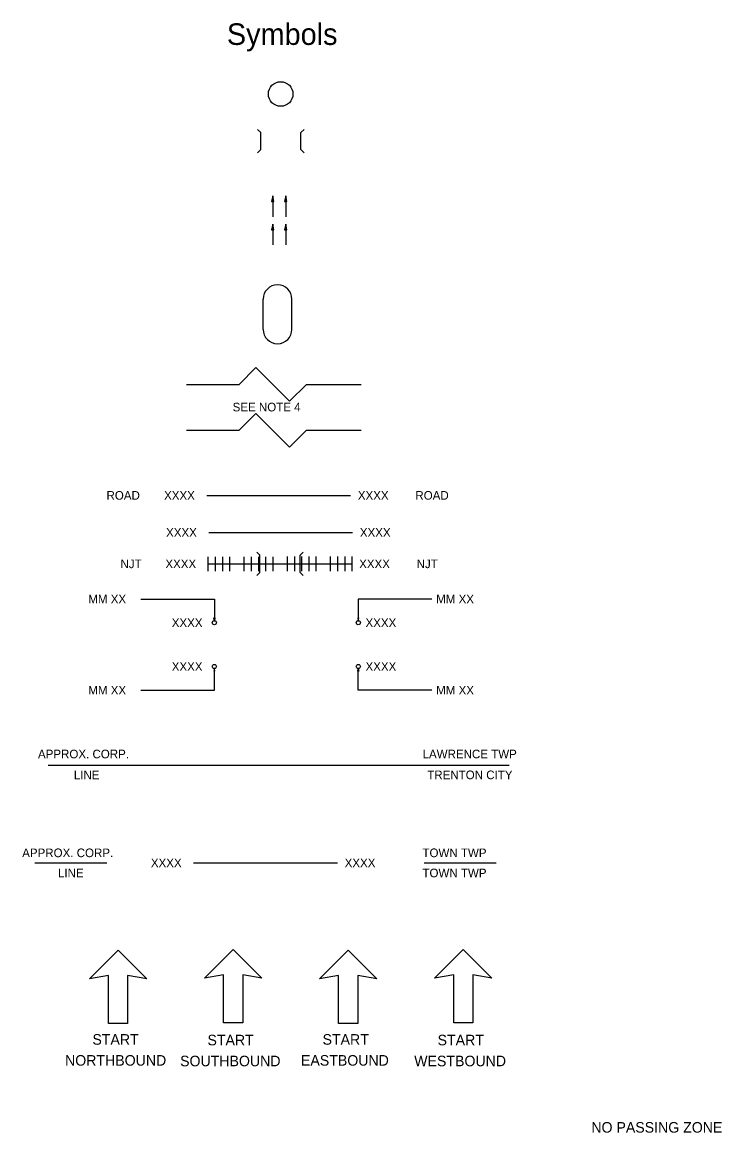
# Model space of a CAD drawing. Extents: x -6359 to 1641, y 3001 to 24737.
# Drawn here: x -4211 to 653, y 3001 to 10724 of the extents above; entities that cross this region are included whole.
import ezdxf

# ---------------------------------------------------------------- set-up
doc = ezdxf.new("R2010")
doc.units = 0
doc.layers.add('_Notes', color=7, linetype='Continuous')

msp = doc.modelspace()

# ---------------------------------------------------------------- linework, layer by layer
at = {"layer": '_Notes'}
for p, q in [((-2553.2, 9957.4), (-2574.4, 9978.6)), ((-2273.2, 9957.4), (-2252, 9978.6)), ((-2553.2, 9837.4), (-2553.2, 9957.4)), ((-2273.2, 9837.4), (-2273.2, 9957.4)), ((-2574.4, 9816.1), (-2553.2, 9837.4)), ((-2252, 9816.1), (-2273.2, 9837.4)), ((-2469.7, 9515.4), (-2469.7, 9370.5)), ((-2379, 9515.4), (-2379, 9370.5)), ((-2469.7, 9319.3), (-2469.7, 9174.4)), ((-2379, 9319.3), (-2379, 9174.4)), ((-2536, 8587.7), (-2536, 8797.7)), ((-2336, 8587.7), (-2336, 8797.7)), ((-2703.4, 8205.1), (-2586.6, 8321.9)), ((-2586.6, 8321.9), (-2352.8, 8088.2)), ((-3068.9, 8205.1), (-2703.4, 8205.1)), ((-2352.8, 8088.2), (-2235.8, 8205.1)), ((-2235.8, 8205.1), (-1853.9, 8205.1)), ((-2703.4, 7885.7), (-2586.6, 8002.5)), ((-2586.6, 8002.5), (-2352.8, 7768.8)), ((-3068.9, 7885.7), (-2703.4, 7885.7)), ((-2352.8, 7768.8), (-2235.8, 7885.7)), ((-2235.8, 7885.7), (-1853.9, 7885.7)), ((-2928.6, 7433.2), (-2428.2, 7433.2)), ((-2428.2, 7433.2), (-1927.7, 7433.2)), ((-2914.6, 7175.7), (-2414.2, 7175.7)), ((-2414.2, 7175.7), (-1913.7, 7175.7)), ((-2559.1, 7017.3), (-2580.3, 7038.5)), ((-2279.1, 7017.3), (-2257.8, 7038.5)), ((-2919.5, 7007.1), (-2919.5, 6907.1)), ((-2919.5, 6957.1), (-2419.1, 6957.3)), ((-2869.5, 7007.1), (-2869.5, 6907.1)), ((-2819.5, 7007.1), (-2819.5, 6907.1)), ((-2769.5, 7007.1), (-2769.5, 6907.1)), ((-2669.5, 7007.1), (-2669.5, 6907.1)), ((-2619.5, 7007.1), (-2619.5, 6907.1)), ((-2569.5, 7007.1), (-2569.5, 6907.1)), ((-2559.1, 6897.3), (-2559.1, 7017.3)), ((-2519.5, 7007.1), (-2519.5, 6907.1)), ((-2469.5, 7007.1), (-2469.5, 6907.1)), ((-2419.1, 6957.3), (-1918.6, 6957.3)), ((-2369.1, 7007.3), (-2369.1, 6907.3)), ((-2319.1, 7007.3), (-2319.1, 6907.3)), ((-2279.1, 6897.3), (-2279.1, 7017.3)), ((-2269.1, 7007.3), (-2269.1, 6907.3)), ((-2219.1, 7007.3), (-2219.1, 6907.3)), ((-2169.1, 7007.3), (-2169.1, 6907.3)), ((-2069.1, 7007.3), (-2069.1, 6907.3)), ((-2019.1, 7007.3), (-2019.1, 6907.3)), ((-1969.1, 7007.3), (-1969.1, 6907.3)), ((-1919.1, 7007.3), (-1919.1, 6907.3)), ((-2580.3, 6876.1), (-2559.1, 6897.3)), ((-2257.8, 6876.1), (-2279.1, 6897.3)), ((-3386.4, 6712), (-2875.3, 6712)), ((-2875.3, 6712), (-2875.3, 6561.8)), ((-1874.4, 6712), (-1874.4, 6561.8)), ((-1363.3, 6712), (-1874.4, 6712)), ((-2875.3, 6079.3), (-2875.3, 6229.4)), ((-1874.4, 6079.3), (-1874.4, 6229.4)), ((-3386.4, 6079.3), (-2875.3, 6079.3)), ((-1363.3, 6079.3), (-1874.4, 6079.3)), ((-4031.2, 5556.5), (-3531.2, 5556.5)), ((-3531.2, 5556.5), (-1324.5, 5556.5)), ((-1324.5, 5556.5), (-824.5, 5556.5)), ((-4123.3, 4877.6), (-3623.3, 4877.6)), ((-3020.4, 4877.6), (-2519.9, 4877.6)), ((-2519.9, 4877.6), (-2019.4, 4877.6)), ((-1416.5, 4877.6), (-916.5, 4877.6)), ((-3744.3, 4072), (-3544.8, 4271.5)), ((-3544.8, 4271.5), (-3345.4, 4072)), ((-2944.3, 4076.3), (-2744.8, 4275.8)), ((-2744.8, 4275.8), (-2545.4, 4076.3)), ((-2144.3, 4072), (-1944.8, 4271.5)), ((-1944.8, 4271.5), (-1745.4, 4072)), ((-1344.3, 4076.3), (-1144.8, 4275.8)), ((-1144.8, 4275.8), (-945.4, 4076.3)), ((-3611.3, 4094.2), (-3744.3, 4072)), ((-3611.3, 3761.7), (-3611.3, 4094.2)), ((-3345.4, 4072), (-3478.3, 4094.2)), ((-3478.3, 4094.2), (-3478.3, 3761.7)), ((-2811.3, 4098.5), (-2944.3, 4076.3)), ((-2811.3, 3766), (-2811.3, 4098.5)), ((-2545.4, 4076.3), (-2678.3, 4098.5)), ((-2678.3, 4098.5), (-2678.3, 3766)), ((-2011.3, 4094.2), (-2144.3, 4072)), ((-2011.3, 3761.7), (-2011.3, 4094.2)), ((-1745.4, 4072), (-1878.3, 4094.2)), ((-1878.3, 4094.2), (-1878.3, 3761.7)), ((-1211.3, 4098.5), (-1344.3, 4076.3)), ((-1211.3, 3766), (-1211.3, 4098.5)), ((-945.4, 4076.3), (-1078.3, 4098.5)), ((-1078.3, 4098.5), (-1078.3, 3766)), ((-3478.3, 3761.7), (-3611.3, 3761.7)), ((-2678.3, 3766), (-2811.3, 3766)), ((-1878.3, 3761.7), (-2011.3, 3761.7)), ((-1078.3, 3766), (-1211.3, 3766))]:
    msp.add_line(p, q, dxfattribs=at)
for points in [[(-2461.7, 9477), (-2469.7, 9515.4), (-2477.7, 9477)], [(-2371, 9477), (-2379, 9515.4), (-2387, 9477)], [(-2461.7, 9280.9), (-2469.7, 9319.3), (-2477.7, 9280.9)], [(-2371, 9280.9), (-2379, 9319.3), (-2387, 9280.9)], [(-2871.3, 6581), (-2875.3, 6561.8), (-2879.3, 6581)], [(-1878.4, 6581), (-1874.4, 6561.8), (-1870.4, 6581)], [(-2871.3, 6210.2), (-2875.3, 6229.4), (-2879.3, 6210.2)], [(-1878.4, 6210.2), (-1874.4, 6229.4), (-1870.4, 6210.2)]]:
    msp.add_lwpolyline(points, close=True, dxfattribs=at)
for centre, radius in [((-2414.3, 10224.4), 85.4), ((-2875.3, 6547.8), 14.1), ((-1874.4, 6547.8), 14.1), ((-2875.3, 6243.5), 14.1), ((-1874.4, 6243.5), 14.1)]:
    msp.add_circle(centre, radius, dxfattribs=at)
for centre, start, end in [((-2436, 8797.7), 90, 180), ((-2436, 8797.7), 0, 90), ((-2436, 8587.7), 180, 270), ((-2436, 8587.7), 270, 0)]:
    msp.add_arc(centre, 100, start, end, dxfattribs=at)

# ---------------------------------------------------------------- texts
for s, height, p in [('Symbols', 150, (-2788.2, 10565.6)), ('SEE NOTE 4 ', 60, (-2748.4, 8017.2)), ('ROAD', 60, (-3625.1, 7403.2)), ('XXXX', 60, (-3224.9, 7403.2)), ('XXXX', 60, (-1877.7, 7403.2)), ('ROAD', 60, (-1477.7, 7403.2)), ('XXXX', 60, (-3211, 7145.7)), ('XXXX', 60, (-1863.7, 7145.7)), ('NJT', 60, (-3528, 6927.3)), ('XXXX', 60, (-3215.8, 6927.3)), ('XXXX', 60, (-1868.6, 6927.3)), ('NJT', 60, (-1469.1, 6927.3)), ('MM XX', 60, (-3751.7, 6682.6)), ('MM XX', 60, (-1333.1, 6682.6)), ('XXXX', 60, (-3171.6, 6517.8)), ('XXXX', 60, (-1824.4, 6517.8)), ('XXXX', 60, (-3171.6, 6213.5)), ('XXXX', 60, (-1824.4, 6213.5)), ('MM XX', 60, (-3751.7, 6048.7)), ('MM XX', 60, (-1333.1, 6048.7)), ('APPROX. CORP.', 60, (-4101.6, 5604.9)), ('LAWRENCE TWP', 60, (-1427.6, 5604.9)), ('LINE', 60, (-3852.4, 5459.8)), ('TRENTON CITY', 60, (-1395.1, 5459.8)), ('APPROX. CORP.', 60, (-4211.3, 4917.6)), ('TOWN TWP', 60, (-1428.5, 4917.6)), ('XXXX', 60, (-3316.7, 4847.6)), ('XXXX', 60, (-1969.4, 4847.6)), ('LINE', 60, (-3962.7, 4777.6)), ('TOWN TWP', 60, (-1428.5, 4777.6)), ('NO PASSING ZONE', 73.42, (-254.2, 3002))]:
    msp.add_text(s, height=height, dxfattribs=at).set_placement(p)
for s, p in [('START', (-3723.1, 3613.4)), ('START', (-2923.1, 3609.1)), ('START', (-2123.1, 3613.4)), ('START', (-1323.1, 3609.1)), ('NORTHBOUND', (-3913.4, 3467.8)), ('SOUTHBOUND', (-3113.4, 3463.5)), ('EASTBOUND', (-2273, 3467.8)), ('WESTBOUND', (-1485.6, 3463.5))]:
    msp.add_text(s, height=73.42, rotation=360, dxfattribs=at).set_placement(p)

doc.saveas('drawing.dxf')
